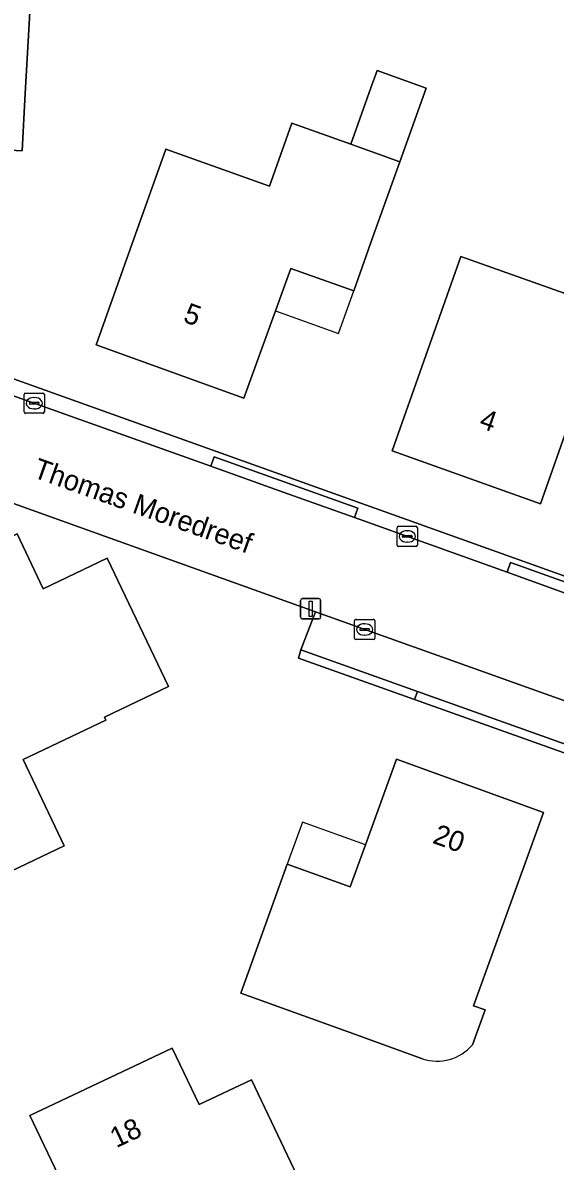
# Model space of a CAD drawing. Extents: x 163266 to 164362, y 381528 to 382286.
# Drawn here: x 163633.8 to 163660, y 381629.2 to 381685.3 of the extents above; entities that cross this region are included whole.
import ezdxf

# ---------------------------------------------------------------- set-up
doc = ezdxf.new("R2010")
doc.units = 0
for name, color, linetype in [('IMGEO_Erf', 7, 'Continuous'), ('IMGEO_Kolk', 7, 'Continuous'), ('IMGEO_Lichtmast', 7, 'Continuous'), ('IMGEO_Openbare_ruimte_label', 7, 'Continuous'), ('IMGEO_Pand', 7, 'Continuous'), ('IMGEO_Pand_nummerreeks', 7, 'Continuous'), ('IMGEO_Pand_overbouw', 7, 'Continuous'), ('IMGEO_Parkeervlak_open', 7, 'Continuous'), ('IMGEO_Rijbaan_lokaal_open', 7, 'Continuous'), ('IMGEO_Voetpad_open', 7, 'Continuous')]:
    doc.layers.add(name, color=color, linetype=linetype)

msp = doc.modelspace()

# ---------------------------------------------------------------- linework, layer by layer
at = {"layer": 'IMGEO_Erf'}
for points in [[(163630.045, 381672.483), (163622.26, 381672.933), (163622.545, 381677.925), (163622.841, 381683.109), (163623.419, 381683.076), (163623.607, 381686.383), (163628.458, 381686.107), (163634.117, 381685.785), (163633.89, 381681.792), (163633.729, 381678.958), (163630.424, 381679.148), (163630.301, 381676.99)], [(163652.35, 381678.42), (163651.006, 381674.668), (163650.071, 381672.058), (163646.979, 381673.165), (163646.22, 381671.07), (163644.664, 381666.775), (163637.378, 381669.407), (163639.061, 381674.116), (163640.82, 381679.04), (163645.92, 381677.22), (163647.03, 381680.33), (163649.928, 381679.289), (163650.92, 381682.056), (163651.228, 381682.917), (163653.64, 381682.051)], [(163660.437, 381671.946), (163661.539, 381675.054), (163666.879, 381673.163), (163665.554, 381669.421), (163664.643, 381666.85), (163661.536, 381667.951), (163660.777, 381665.808), (163659.277, 381661.572), (163651.959, 381664.169), (163653.629, 381668.882), (163655.352, 381673.746)], [(163635.811, 381644.72), (163629.88, 381641.895), (163626.086, 381649.857), (163629.066, 381651.277), (163628.4, 381652.675), (163626.469, 381656.729), (163633.483, 381660.082), (163634.774, 381657.374), (163637.931, 381658.883), (163640.943, 381652.564), (163637.785, 381651.055), (163637.858, 381650.901), (163633.788, 381648.962)], [(163642.451, 381631.971), (163645.039, 381633.188), (163649.24, 381624.353), (163647.508, 381623.539), (163646.25, 381623.982), (163645.49, 381625.58), (163640.6, 381623.28), (163642.01, 381620.29), (163636.903, 381617.844), (163633.799, 381624.303), (163636.83, 381625.741), (163636.05, 381627.37), (163634.12, 381631.42), (163641.13, 381634.75)]]:
    msp.add_lwpolyline(points, close=True, dxfattribs=at)
for points in [[(163629.716, 381668.998), (163704.116, 381642.385), (163714.571, 381647.298), (163714.503, 381647.459), (163712.507, 381651.662), (163712.236, 381651.529), (163710.461, 381655.144), (163718.518, 381659.102), (163719.518, 381657.066), (163722.573, 381658.314), (163723.351, 381656.715), (163727.31, 381654.748), (163727.79, 381653.802)], [(163653.06, 381651.93), (163647.357, 381653.958), (163647.464, 381654.37), (163648.186, 381656.239), (163629.853, 381662.817)], [(163581.284, 381602.447), (163586.783, 381590.674), (163589.374, 381591.224), (163593.379, 381593.084), (163622.355, 381606.539), (163623.496, 381604.168), (163677.889, 381629.916), (163692.948, 381637.102), (163693.217, 381637.23), (163693.201, 381637.598), (163686.863, 381639.858), (163679.05, 381642.678), (163675.489, 381643.937), (163670.794, 381645.621), (163667.214, 381646.884), (163653.06, 381651.93)], [(163653.457, 381634.224), (163649.802, 381635.545), (163644.505, 381637.46), (163646.801, 381643.81), (163649.903, 381642.688), (163650.654, 381644.765), (163652.179, 381648.983), (163659.425, 381646.357)], [(163659.425, 381646.357), (163655.981, 381636.832), (163656.55, 381636.626), (163655.931, 381634.914)]]:
    msp.add_lwpolyline(points, dxfattribs=at)
msp.add_arc((163654.182, 381636.403), 2.297, 251.5872, 319.5804, dxfattribs=at)
at = {"layer": 'IMGEO_Kolk'}
for p, q in [((163633.827, 381666.099), (163633.827, 381666.951)), ((163633.902, 381667.025), (163634.754, 381667.025)), ((163634.315, 381666.805), (163634.34, 381666.805)), ((163634.828, 381666.951), (163634.828, 381666.099)), ((163634.086, 381666.519), (163634.086, 381666.531)), ((163634.524, 381666.482), (163634.126, 381666.482)), ((163634.129, 381666.568), (163634.527, 381666.568)), ((163634.338, 381666.245), (163634.313, 381666.245)), ((163634.57, 381666.531), (163634.57, 381666.519)), ((163634.754, 381666.025), (163633.902, 381666.025)), ((163652.211, 381659.532), (163652.211, 381660.384)), ((163652.286, 381660.458), (163653.138, 381660.458)), ((163652.47, 381659.952), (163652.47, 381659.964)), ((163652.513, 381660.001), (163652.911, 381660.001)), ((163652.699, 381660.238), (163652.724, 381660.238)), ((163652.954, 381659.964), (163652.954, 381659.952)), ((163653.212, 381660.384), (163653.212, 381659.532)), ((163653.138, 381659.458), (163652.286, 381659.458)), ((163652.908, 381659.915), (163652.51, 381659.915)), ((163652.722, 381659.678), (163652.697, 381659.678)), ((163650.11, 381654.948), (163650.11, 381655.8)), ((163650.185, 381655.874), (163651.037, 381655.874)), ((163650.598, 381655.654), (163650.623, 381655.654)), ((163651.111, 381655.8), (163651.111, 381654.948)), ((163650.369, 381655.368), (163650.369, 381655.38)), ((163650.807, 381655.331), (163650.409, 381655.331)), ((163650.412, 381655.417), (163650.81, 381655.417)), ((163650.621, 381655.094), (163650.596, 381655.094)), ((163650.853, 381655.38), (163650.853, 381655.368)), ((163651.037, 381654.874), (163650.185, 381654.874))]:
    msp.add_line(p, q, dxfattribs=at)
for points in [[(163633.827, 381666.099), (163633.827, 381666.951)], [(163633.902, 381667.025), (163634.754, 381667.025)], [(163634.828, 381666.951), (163634.828, 381666.099)], [(163634.754, 381666.025), (163633.902, 381666.025)], [(163652.211, 381659.532), (163652.211, 381660.384)], [(163652.286, 381660.458), (163653.138, 381660.458)], [(163653.212, 381660.384), (163653.212, 381659.532)], [(163653.138, 381659.458), (163652.286, 381659.458)], [(163650.11, 381654.948), (163650.11, 381655.8)], [(163650.185, 381655.874), (163651.037, 381655.874)], [(163651.111, 381655.8), (163651.111, 381654.948)], [(163651.037, 381654.874), (163650.185, 381654.874)]]:
    msp.add_lwpolyline(points, dxfattribs=at)
for centre, radius, start, end in [((163633.904, 381666.949), 0.0765, 91.552, 178.448), ((163633.904, 381666.949), 0.0765, 91.552, 178.448), ((163634.752, 381666.949), 0.0765, 1.552, 88.448), ((163634.752, 381666.949), 0.0765, 1.552, 88.448), ((163634.126, 381666.528), 0.0403, 85.8775, 175.7526), ((163634.123, 381666.518), 0.0366, 178.938, 274.7102), ((163634.527, 381666.525), 0.043, 264.8664, 352.4533), ((163634.531, 381666.53), 0.0386, 1.7309, 96.639), ((163633.904, 381666.101), 0.0765, 181.552, 268.448), ((163633.904, 381666.101), 0.0765, 181.552, 268.448), ((163634.752, 381666.101), 0.0765, 271.552, 358.448), ((163634.752, 381666.101), 0.0765, 271.552, 358.448), ((163652.288, 381660.382), 0.0765, 91.552, 178.448), ((163652.288, 381660.382), 0.0765, 91.552, 178.448), ((163652.51, 381659.961), 0.0403, 85.8775, 175.7526), ((163652.507, 381659.951), 0.0366, 178.938, 274.7102), ((163652.911, 381659.958), 0.043, 264.8664, 352.4533), ((163652.915, 381659.963), 0.0386, 1.7309, 96.639), ((163653.136, 381660.382), 0.0765, 1.552, 88.448), ((163653.136, 381660.382), 0.0765, 1.552, 88.448), ((163652.288, 381659.534), 0.0765, 181.552, 268.448), ((163652.288, 381659.534), 0.0765, 181.552, 268.448), ((163653.136, 381659.534), 0.0765, 271.552, 358.448), ((163653.136, 381659.534), 0.0765, 271.552, 358.448), ((163650.187, 381655.798), 0.0765, 91.552, 178.448), ((163650.187, 381655.798), 0.0765, 91.552, 178.448), ((163651.035, 381655.798), 0.0765, 1.552, 88.448), ((163651.035, 381655.798), 0.0765, 1.552, 88.448), ((163650.187, 381654.95), 0.0765, 181.552, 268.448), ((163650.187, 381654.95), 0.0765, 181.552, 268.448), ((163650.409, 381655.377), 0.0403, 85.8775, 175.7526), ((163650.406, 381655.367), 0.0366, 178.938, 274.7102), ((163650.81, 381655.374), 0.043, 264.8664, 352.4533), ((163650.814, 381655.379), 0.0386, 1.7309, 96.639), ((163651.035, 381654.95), 0.0765, 271.552, 358.448), ((163651.035, 381654.95), 0.0765, 271.552, 358.448)]:
    msp.add_arc(centre, radius, start, end, dxfattribs=at)
for centre, major_axis, ratio, start_param, end_param in [((163634.314, 381666.525), (-0.387, 0.002), 0.722429, 4.712389, 7.853982), ((163634.339, 381666.525), (-0.39, 0.002), 0.717154, 1.570796, 4.712389), ((163652.698, 381659.958), (-0.387, 0.002), 0.722429, 4.712389, 7.853982), ((163652.723, 381659.958), (-0.39, 0.002), 0.717154, 1.570796, 4.712389), ((163650.597, 381655.374), (-0.387, 0.002), 0.722429, 4.712389, 7.853982), ((163650.622, 381655.374), (-0.39, 0.002), 0.717154, 1.570796, 4.712389)]:
    msp.add_ellipse(centre, major_axis=major_axis, ratio=ratio, start_param=start_param, end_param=end_param, dxfattribs=at)
at = {"layer": 'IMGEO_Lichtmast'}
for p, q in [((163647.453, 381655.994), (163647.453, 381656.794)), ((163647.453, 381656.794), (163647.453, 381655.994)), ((163647.553, 381656.894), (163648.343, 381656.894)), ((163648.343, 381656.894), (163647.553, 381656.894)), ((163648.443, 381656.794), (163648.443, 381655.994)), ((163648.443, 381655.994), (163648.443, 381656.794)), ((163648.343, 381655.894), (163647.553, 381655.894)), ((163647.553, 381655.894), (163648.343, 381655.894))]:
    msp.add_line(p, q, dxfattribs=at)
msp.add_lwpolyline([(163647.873, 381656.769), (163648.023, 381656.769), (163648.023, 381656.019), (163647.873, 381656.019), (163647.873, 381656.769)], dxfattribs=at)
for centre, start, end in [((163647.553, 381656.794), 90, 180), ((163647.553, 381656.794), 90, 180), ((163648.343, 381656.794), 0, 90), ((163648.343, 381656.794), 360, 90), ((163647.553, 381655.994), 180, 270), ((163647.553, 381655.994), 180, 270), ((163648.343, 381655.994), 270, 0), ((163648.343, 381655.994), 270, 0)]:
    msp.add_arc(centre, 0.1, start, end, dxfattribs=at)
at = {"layer": 'IMGEO_Pand'}
for points in [[(163633.89, 381681.792), (163634.117, 381685.785), (163628.458, 381686.107), (163623.607, 381686.383), (163623.419, 381683.076), (163622.841, 381683.109), (163622.545, 381677.925), (163622.26, 381672.933), (163630.045, 381672.483), (163630.301, 381676.99), (163630.424, 381679.148), (163633.729, 381678.958)], [(163649.928, 381679.289), (163652.35, 381678.42), (163653.64, 381682.051), (163651.228, 381682.917), (163650.92, 381682.056)], [(163651.006, 381674.668), (163652.35, 381678.42), (163649.928, 381679.289), (163647.03, 381680.33), (163645.92, 381677.22), (163640.82, 381679.04), (163639.061, 381674.116), (163637.378, 381669.407), (163644.664, 381666.775), (163646.22, 381671.07), (163646.979, 381673.165), (163650.071, 381672.058)], [(163665.554, 381669.421), (163666.879, 381673.163), (163661.539, 381675.054), (163660.437, 381671.946), (163655.352, 381673.746), (163653.629, 381668.882), (163651.959, 381664.169), (163659.277, 381661.572), (163660.777, 381665.808), (163661.536, 381667.951), (163664.643, 381666.85)], [(163637.858, 381650.901), (163637.785, 381651.055), (163640.943, 381652.564), (163637.931, 381658.883), (163634.774, 381657.374), (163633.483, 381660.082), (163626.469, 381656.729), (163628.4, 381652.675), (163629.066, 381651.277), (163626.086, 381649.857), (163629.88, 381641.895), (163635.811, 381644.72), (163633.788, 381648.962)], [(163641.13, 381634.75), (163634.12, 381631.42), (163636.05, 381627.37), (163636.83, 381625.741), (163633.799, 381624.303), (163636.903, 381617.844), (163642.01, 381620.29), (163640.6, 381623.28), (163645.49, 381625.58), (163646.25, 381623.982), (163647.508, 381623.539), (163649.24, 381624.353), (163645.039, 381633.188), (163642.451, 381631.971)]]:
    msp.add_lwpolyline(points, close=True, dxfattribs=at)
for points in [[(163659.425, 381646.357), (163652.179, 381648.983), (163650.654, 381644.765), (163649.903, 381642.688), (163646.801, 381643.81), (163644.505, 381637.46), (163649.802, 381635.545), (163653.457, 381634.224)], [(163655.931, 381634.914), (163656.55, 381636.626), (163655.981, 381636.832), (163659.425, 381646.357)]]:
    msp.add_lwpolyline(points, dxfattribs=at)
msp.add_arc((163654.182, 381636.403), 2.297, 251.5872, 319.5804, dxfattribs=at)
at = {"layer": 'IMGEO_Pand_overbouw'}
for points in [[(163650.071, 381672.058), (163646.979, 381673.165), (163646.22, 381671.07), (163649.32, 381669.96)], [(163650.654, 381644.765), (163647.552, 381645.887), (163646.801, 381643.81), (163649.903, 381642.688)]]:
    msp.add_lwpolyline(points, close=True, dxfattribs=at)
at = {"layer": 'IMGEO_Parkeervlak_open'}
msp.add_lwpolyline([(163696.905, 381638.85), (163687.483, 381642.223), (163648.186, 381656.239), (163647.464, 381654.37), (163653.209, 381652.324), (163667.36, 381647.283), (163670.924, 381646.013), (163675.637, 381644.335), (163679.195, 381643.067), (163687.117, 381640.288), (163693.409, 381638.078)], dxfattribs=at)
at = {"layer": 'IMGEO_Rijbaan_lokaal_open'}
for points in [[(163705.423, 381641.228), (163704.64, 381641.399), (163701.053, 381642.681), (163690.54, 381646.438), (163686.952, 381647.72), (163675.841, 381651.691), (163672.283, 381652.963), (163665.837, 381655.241), (163664.921, 381655.593), (163661.583, 381656.764), (163661.21, 381656.897), (163657.637, 381658.197), (163650.107, 381660.888), (163646.599, 381662.142), (163643.027, 381663.418), (163633.033, 381666.99), (163629.463, 381668.266), (163629.085, 381668.401)], [(163629.853, 381662.817), (163648.186, 381656.239), (163687.483, 381642.223), (163696.905, 381638.85), (163698.391, 381638.347), (163700.047, 381637.754), (163707.897, 381641.593)]]:
    msp.add_lwpolyline(points, dxfattribs=at)
at = {"layer": 'IMGEO_Voetpad_open'}
for points in [[(163704.116, 381642.385), (163629.716, 381668.998)], [(163633.033, 381666.99), (163643.027, 381663.418), (163643.195, 381663.888), (163650.275, 381661.358), (163650.107, 381660.888), (163657.637, 381658.197), (163657.805, 381658.667), (163661.385, 381657.388), (163661.21, 381656.897), (163661.583, 381656.764), (163661.829, 381657.472), (163665.162, 381656.282), (163664.921, 381655.593), (163665.837, 381655.241), (163672.283, 381652.963), (163672.451, 381653.433), (163676.009, 381652.161), (163675.841, 381651.691), (163686.952, 381647.72), (163687.12, 381648.19), (163690.708, 381646.908), (163690.54, 381646.438), (163701.053, 381642.681)]]:
    msp.add_lwpolyline(points, dxfattribs=at)
for points in [[(163650.107, 381660.888), (163650.275, 381661.358), (163643.195, 381663.888), (163643.027, 381663.418), (163646.599, 381662.142)], [(163661.21, 381656.897), (163661.385, 381657.388), (163657.805, 381658.667), (163657.637, 381658.197)], [(163647.357, 381653.958), (163653.06, 381651.93), (163653.209, 381652.324), (163647.464, 381654.37)], [(163667.214, 381646.884), (163667.36, 381647.283), (163653.209, 381652.324), (163653.06, 381651.93)]]:
    msp.add_lwpolyline(points, close=True, dxfattribs=at)

# ---------------------------------------------------------------- texts
at = {"layer": 'IMGEO_Openbare_ruimte_label'}
msp.add_text('Thomas Moredreef', height=1, rotation=340.3693, dxfattribs=at).set_placement((163634.209, 381662.898))
at = {"layer": 'IMGEO_Pand_nummerreeks'}
for s, rotation, p in [('5', 340.1356, (163641.618, 381670.554)), ('4', 340.4621, (163656.202, 381665.338)), ('20', 340.0783, (163653.91, 381644.868)), ('18', 25.4107, (163638.371, 381629.809))]:
    msp.add_text(s, height=1, rotation=rotation, dxfattribs=at).set_placement(p)

doc.saveas('drawing.dxf')
